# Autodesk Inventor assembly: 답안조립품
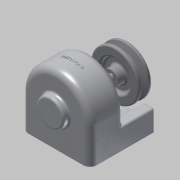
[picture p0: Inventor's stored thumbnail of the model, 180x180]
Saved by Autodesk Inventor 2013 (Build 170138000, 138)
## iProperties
Created: 2015-02
Part Number: 답안조립품
Document SubType Name: Assembly
Designer: Administrator
Author: Administrator
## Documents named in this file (14)
- C:\Users\Administrator\Desktop\450216V1020\답안조립품.iam
- C:\Users\Administrator\Desktop\450216V1020\본체.ipt
- C:\Users\Administrator\Desktop\450216V1020\M3x0.5.ipt
- C:\Users\Administrator\Desktop\450216V1020\M5x0.8.ipt
- M5x0.8.ipt
- C:\Users\Administrator\Desktop\450216V1020\V-벨트폴리.ipt
- C:\Users\Administrator\Desktop\450216V1020\베어링 6001.ipt
- C:\Users\Administrator\Desktop\450216V1020\스퍼기어.ipt
- C:\Users\Administrator\Desktop\450216V1020\오일실.ipt
- C:\Users\Administrator\Desktop\450216V1020\와샤.ipt
- C:\Users\Administrator\Desktop\450216V1020\축.ipt
- C:\Users\Administrator\Desktop\450216V1020\축커버.ipt
- C:\Users\Administrator\Desktop\450216V1020\키4x4.ipt
- C:\Users\Administrator\Desktop\450216V1020\키5x5.ipt
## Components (6 placed, 3 different names)
1. M5x0.8:1 — 각도:1
2. V-벨트폴리:1
3. M3x0.5:1
4. M3x0.5:2
5. M3x0.5:3
6. M3x0.5:4
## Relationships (1: Angle 1)
- 각도:1 [Angle]: M5x0.8:1
